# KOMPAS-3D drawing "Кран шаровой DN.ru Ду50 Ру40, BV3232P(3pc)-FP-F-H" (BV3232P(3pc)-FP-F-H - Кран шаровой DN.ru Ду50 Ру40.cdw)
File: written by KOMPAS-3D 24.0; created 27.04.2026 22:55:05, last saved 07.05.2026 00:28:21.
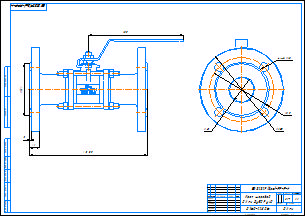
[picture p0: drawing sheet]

Document properties: Автор: Максим; Форматы листов документа: A2; Полное имя файла: BVxxP(3pc)-FP-F-H - Кран шаровой DN.ru Ду50 Ру40.cdw; Масса: 8.07; Наименование: Кран шаровой DN.ru Ду50 Ру40; Количество листов документа: 1; Примечание: D160-22806

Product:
- Body: Тело 1  | qty 1
    Масса: 8.142065
- Part/product: Кран шаровой DN.ru Ду50 Ру40  | designation BV3232P(3pc)-FP-F-H
    Масса: 8.07
    Раздел спецификации: Прочие изделия
    Форматы листов документа: A2
    Примечание: D160-22806

Views: Вид 1, Вид:1, Проекционный вид 2
Referenced files in D:\Rabota ebanaya\Апрель\BVxxP(3pc)-FP-F-H Кран шаровой Ду15-100\Исходники\DN50\: BVxxP(3pc)-FP-F-H - Кран шаровой DN.ru Ду50 Ру40.m3d, BVxxP(3pc)-FP-F-H - Кран шаровой DN.ru Ду50 Ру40.cdw
Referenced files in D:\Rabota ebanaya\Апрель\BV3232P(3pc)-FP-F-H Кран шаровой Ду15-100\Исходники\DN50\: BV3232P(3pc)-FP-F-H - Кран шаровой DN.ru Ду50 Ру40.m3d
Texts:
  Линейный размер
  BV3232P(3pc)-FP-F-H
  Диаметральный размер
  Кран шаровой
  DN.ru Ду50 Ру40
  Кран шаровой DN.ru Ду50 Ру40
  BV3232P(3pc)-FP-F-H Кран шаровой DN.ru Ду50 Ру40
Dimensions and other numbers on the sheet: 0; 3; 2; 4; 230±1,5; 102; 20; 185; 49; 4 отв.; 18; 165; 125; 1:1; 1; 8,07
